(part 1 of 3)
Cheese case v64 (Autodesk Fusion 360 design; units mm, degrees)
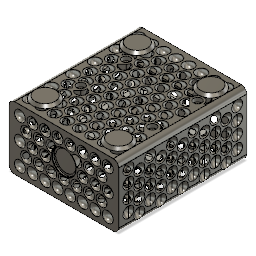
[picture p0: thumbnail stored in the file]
parameter "thickness" = 6.234
parameter "radius" = 5.3988 (= "thickness * sqrt(3) / 2")
parameter "bootm_width" = 108.8712 (= "2 * hor_idents + bottom_front_big_x * 2 * x - 2 * x + 2 * radius")
parameter "bottom_height" = 127.4117 (= "2 * ver_idents + ( bottom_front_big_y ) * 4 * radius - 2 * radius")
parameter "hor_idents" = 5.3988 (= "radius")
parameter "ver_idents" = 4.319 (= "radius / 1.25")
parameter "minimal_feature" = 1.6704 (= "2 * ( x - radius )")
parameter "front_height" = 62.6261 (= "2 * ver_idents + ( 3 ) * 4 * radius - 2 * radius")
base_feature "Base Feature1"
sketch "Sketch1" plane through (0, 0, 0) normal (0, 0, -1) x axis (-1, 0, 0)
  line L1 (42.5, 25) -> (42.5, -25)
  line L2 (-39.5, 28) -> (39.5, 28)
  line L3 (-42.5, -25) -> (-42.5, 25)
  line L4 (39.5, -28) -> (-39.5, -28)
  arc A1 centre (39.5, 25) radius 3 clockwise from (39.5, 28) to (42.5, 25)
  arc A2 centre (-39.5, 25) radius 3 clockwise from (-42.5, 25) to (-39.5, 28)
  arc A3 centre (-39.5, -25) radius 3 clockwise from (-39.5, -28) to (-42.5, -25)
  arc A4 centre (39.5, -25) radius 3 clockwise from (42.5, -25) to (39.5, -28)
  circle C1 centre (39, -24.5) radius 1.375
  circle C2 centre (-19, 24.5) radius 1.375
  circle C3 centre (-19, -24.5) radius 1.375
  circle C4 centre (39, 24.5) radius 1.375
extrude "Extrude1" add sketch "Sketch1" profile of C4 along a picked direction blind -14.9 named "d69_1"
base_feature "Base Feature1"
base_feature "Base Feature1"
base_feature "Base Feature1"
base_feature "Base Feature1"
base_feature "Base Feature1"
base_feature "Base Feature1"
base_feature "Base Feature1"
position "Position1"
sketch "Sketch1" plane through (0, 0, 0) normal (0, 1, 0) x axis (1, 0, 0)
  line L1 (108.8712, 0) -> (0, 0)
  line L2 (108.8712, 127.4117) -> (108.8712, 0)
  line L3 (0, 127.4117) -> (108.8712, 127.4117)
  line L4 (0, 0) -> (0, 127.4117)
  point P1 (0, 0)
  point P2 (0, 0)
  point P3 (108.8712, 0)
  point P5 (0, 127.4117)
  horizontal L1
  vertical L2
  horizontal L3
  vertical L4
  coincident P1 P2
  dimension "d129" distance P2 P3 = 108.8712 (= "bootm_width")
  dimension "d130" distance P2 P5 = 127.4117 (= "bottom_height")
extrude "Extrude1" new body sketch "Sketch1" along normal blind 6.234 (= "thickness")
position "Position2"
sketch "Sketch2" plane through (0, 0, 0) normal (0, 0, 1) x axis (1, 0, 0)
  line L1 (108.8712, 0) -> (0, 0)
  line L2 (108.8712, 6.234) -> (108.8712, 0)
  line L3 (0, 6.234) -> (108.8712, 6.234)
  line L4 (0, 0) -> (0, 6.234)
  line L5 (108.8712, 6.234) -> (0, 6.234)
  line L6 (108.8712, -56.3921) -> (108.8712, 6.234)
  line L7 (0, -56.3921) -> (108.8712, -56.3921)
  line L8 (0, 6.234) -> (0, -56.3921)
  point P5 (0, 6.234)
  point P6 (0, 6.234)
  point P7 (108.8712, 6.234)
  point P9 (0, -56.3921)
  horizontal L5
  vertical L6
  horizontal L7
  vertical L8
  coincident P5 P6
  dimension "d133" distance P6 P7 = 108.8712 (= "bootm_width")
  dimension "d134" distance P6 P9 = 62.6261 (= "front_height")
position "Position3"
extrude "Extrude2" new body sketch "Sketch2" no distance stored bodies "Vorne"
sketch "Sketch3" plane through (0, 0, 0) normal (0, 0, 1) x axis (1, 0, 0)
  line L1 (108.8712, -56.3921) -> (0, -56.3921)
  line L2 (108.8712, 6.234) -> (108.8712, -56.3921)
  line L3 (0, 6.234) -> (108.8712, 6.234)
  line L4 (0, -56.3921) -> (0, 6.234)
  line L5 (108.8712, -56.3921) -> (0, -56.3921)
  line L6 (108.8712, -50.1581) -> (108.8712, -56.3921)
  line L7 (0, -50.1581) -> (108.8712, -50.1581)
  line L8 (0, -56.3921) -> (0, -50.1581)
  point P2 (0, -56.3921)
  point P6 (0, -56.3921)
  point P7 (108.8712, -56.3921)
  point P9 (0, -50.1581)
  horizontal L5
  vertical L6
  horizontal L7
  vertical L8
  coincident P2 P6
  dimension "d137" distance P6 P7 = 108.8712 (= "bootm_width")
  dimension "d138" distance P6 P9 = 6.234 (= "thickness")
sketch "Sketch4" plane through (108.8712, 0, 0) normal (1, 0, 0) x axis (0, 0, -1)
  line L1 (127.4117, 0) -> (0, 0)
  line L2 (127.4117, 6.234) -> (127.4117, 0)
  line L3 (0, 6.234) -> (127.4117, 6.234)
  line L4 (0, 0) -> (0, 6.234)
  line L5 (127.4117, 6.234) -> (0, 6.234)
  line L6 (127.4117, -56.3921) -> (127.4117, 6.234)
  line L7 (0, -56.3921) -> (127.4117, -56.3921)
  line L8 (0, 6.234) -> (0, -56.3921)
  point P5 (0, 6.234)
  point P6 (0, 6.234)
  point P7 (127.4117, 6.234)
  point P9 (0, -56.3921)
  horizontal L5
  vertical L6
  horizontal L7
  vertical L8
  coincident P5 P6
  dimension "d141" distance P6 P7 = 127.4117 (= "bottom_height")
  dimension "d142" distance P6 P9 = 62.6261 (= "front_height")
extrude "Extrude4" new body sketch "Sketch4" no distance stored bodies "Links"
sketch "Sketch5" plane through (0, 0, 0) normal (-1, 0, 0) x axis (0, 0, 1)
  line L1 (0, 0) -> (-127.4117, 0)
  line L2 (0, 6.234) -> (0, 0)
  line L3 (-127.4117, 6.234) -> (0, 6.234)
  line L4 (-127.4117, 0) -> (-127.4117, 6.234)
  line L5 (-127.4117, 6.234) -> (0, 6.234)
  line L6 (-127.4117, -56.3921) -> (-127.4117, 6.234)
  line L7 (0, -56.3921) -> (-127.4117, -56.3921)
  line L8 (0, 6.234) -> (0, -56.3921)
  point P4 (0, 6.234)
  point P6 (0, 6.234)
  point P7 (-127.4117, 6.234)
  point P9 (0, -56.3921)
  horizontal L5
  vertical L6
  horizontal L7
  vertical L8
  coincident P4 P6
  dimension "d145" distance P6 P7 = 127.4117 (= "bottom_height")
  dimension "d146" distance P6 P9 = 62.6261 (= "front_height")
position "Position4"
position "Position5"
position "Position6"
sketch "Bottom outside" plane through (0, 6.234, 0) normal (0, 1, 0) x axis (-1, 0, 0)
  line L1 (0, 0) -> (0, -127.4117)
  line L2 (-108.8712, 0) -> (0, 0)
  line L3 (-108.8712, -127.4117) -> (-108.8712, 0)
  line L4 (0, -127.4117) -> (-108.8712, -127.4117)
  line L5 (-17.0316, -25.9143) -> (-17.0316, -20.5154)
  line L6 (-10.7976, -15.1166) -> (-10.7976, -9.7178)
  line L7 (-17.0316, -15.1166) -> (-17.0316, -20.5154)
  line L8 (-17.0316, -20.5154) -> (-17.0316, -9.7178)
  line L9 (-10.7976, -4.319) -> (-10.7976, -9.7178)
  line L10 (-17.0316, -9.7178) -> (-10.7976, -9.7178)
  line L11 (-5.3988, -50) -> (-5.3988, 0)
  line L12 (-96.4032, -4.319) -> (0, -4.319)
  line L13 (-29.4996, -25.9143) -> (-29.4996, -20.5154)
  line L14 (-29.4996, -15.1166) -> (-29.4996, -20.5154)
  line L15 (-41.9676, -25.9143) -> (-41.9676, -20.5154)
  line L16 (-41.9676, -15.1166) -> (-41.9676, -20.5154)
  line L17 (-54.4356, -25.9143) -> (-54.4356, -20.5154)
  line L18 (-54.4356, -15.1166) -> (-54.4356, -20.5154)
  line L19 (-66.9036, -25.9143) -> (-66.9036, -20.5154)
  line L20 (-66.9036, -15.1166) -> (-66.9036, -20.5154)
  line L21 (-79.3716, -25.9143) -> (-79.3716, -20.5154)
  line L22 (-79.3716, -15.1166) -> (-79.3716, -20.5154)
  line L23 (-91.8396, -25.9143) -> (-91.8396, -20.5154)
  line L24 (-91.8396, -15.1166) -> (-91.8396, -20.5154)
  line L25 (-17.0316, -47.5095) -> (-17.0316, -42.1107)
  line L26 (-17.0316, -36.7119) -> (-17.0316, -42.1107)
  line L27 (-29.4996, -47.5095) -> (-29.4996, -42.1107)
  line L28 (-29.4996, -36.7119) -> (-29.4996, -42.1107)
  line L29 (-41.9676, -47.5095) -> (-41.9676, -42.1107)
  line L30 (-41.9676, -36.7119) -> (-41.9676, -42.1107)
  line L31 (-54.4356, -47.5095) -> (-54.4356, -42.1107)
  line L32 (-54.4356, -36.7119) -> (-54.4356, -42.1107)
  line L33 (-66.9036, -47.5095) -> (-66.9036, -42.1107)
  line L34 (-66.9036, -36.7119) -> (-66.9036, -42.1107)
  line L35 (-79.3716, -47.5095) -> (-79.3716, -42.1107)
  line L36 (-79.3716, -36.7119) -> (-79.3716, -42.1107)
  line L37 (-91.8396, -47.5095) -> (-91.8396, -42.1107)
  line L38 (-91.8396, -36.7119) -> (-91.8396, -42.1107)
  line L39 (-17.0316, -69.1047) -> (-17.0316, -63.7059)
  line L40 (-17.0316, -58.3071) -> (-17.0316, -63.7059)
  line L41 (-29.4996, -69.1047) -> (-29.4996, -63.7059)
  line L42 (-29.4996, -58.3071) -> (-29.4996, -63.7059)
  line L43 (-41.9676, -69.1047) -> (-41.9676, -63.7059)
  line L44 (-41.9676, -58.3071) -> (-41.9676, -63.7059)
  line L45 (-54.4356, -69.1047) -> (-54.4356, -63.7059)
  line L46 (-54.4356, -58.3071) -> (-54.4356, -63.7059)
  line L47 (-66.9036, -69.1047) -> (-66.9036, -63.7059)
  line L48 (-66.9036, -58.3071) -> (-66.9036, -63.7059)
  line L49 (-79.3716, -69.1047) -> (-79.3716, -63.7059)
  line L50 (-79.3716, -58.3071) -> (-79.3716, -63.7059)
  line L51 (-91.8396, -69.1047) -> (-91.8396, -63.7059)
  line L52 (-91.8396, -58.3071) -> (-91.8396, -63.7059)
  line L53 (-17.0316, -90.6999) -> (-17.0316, -85.3011)
  line L54 (-17.0316, -79.9023) -> (-17.0316, -85.3011)
  line L55 (-29.4996, -90.6999) -> (-29.4996, -85.3011)
  line L56 (-29.4996, -79.9023) -> (-29.4996, -85.3011)
  line L57 (-41.9676, -90.6999) -> (-41.9676, -85.3011)
  line L58 (-41.9676, -79.9023) -> (-41.9676, -85.3011)
  line L59 (-54.4356, -90.6999) -> (-54.4356, -85.3011)
  line L60 (-54.4356, -79.9023) -> (-54.4356, -85.3011)
  line L61 (-66.9036, -90.6999) -> (-66.9036, -85.3011)
  line L62 (-66.9036, -79.9023) -> (-66.9036, -85.3011)
  line L63 (-79.3716, -90.6999) -> (-79.3716, -85.3011)
  line L64 (-79.3716, -79.9023) -> (-79.3716, -85.3011)
  line L65 (-91.8396, -90.6999) -> (-91.8396, -85.3011)
  line L66 (-91.8396, -79.9023) -> (-91.8396, -85.3011)
  line L67 (-23.2656, -15.1166) -> (-23.2656, -9.7178)
  line L68 (-23.2656, -4.319) -> (-23.2656, -9.7178)
  line L69 (-35.7336, -15.1166) -> (-35.7336, -9.7178)
  line L70 (-35.7336, -4.319) -> (-35.7336, -9.7178)
  line L71 (-48.2016, -15.1166) -> (-48.2016, -9.7178)
  line L72 (-48.2016, -4.319) -> (-48.2016, -9.7178)
  line L73 (-60.6696, -15.1166) -> (-60.6696, -9.7178)
  line L74 (-60.6696, -4.319) -> (-60.6696, -9.7178)
  line L75 (-73.1376, -15.1166) -> (-73.1376, -9.7178)
  line L76 (-73.1376, -4.319) -> (-73.1376, -9.7178)
  line L77 (-85.6056, -15.1166) -> (-85.6056, -9.7178)
  line L78 (-85.6056, -4.319) -> (-85.6056, -9.7178)
  line L79 (-98.0736, -15.1166) -> (-98.0736, -9.7178)
  line L80 (-98.0736, -4.319) -> (-98.0736, -9.7178)
  line L81 (-10.7976, -36.7119) -> (-10.7976, -31.3131)
  line L82 (-10.7976, -25.9143) -> (-10.7976, -31.3131)
  line L83 (-23.2656, -36.7119) -> (-23.2656, -31.3131)
  line L84 (-23.2656, -25.9143) -> (-23.2656, -31.3131)
  line L85 (-35.7336, -36.7119) -> (-35.7336, -31.3131)
  line L86 (-35.7336, -25.9143) -> (-35.7336, -31.3131)
  line L87 (-48.2016, -36.7119) -> (-48.2016, -31.3131)
  line L88 (-48.2016, -25.9143) -> (-48.2016, -31.3131)
  line L89 (-60.6696, -36.7119) -> (-60.6696, -31.3131)
  line L90 (-60.6696, -25.9143) -> (-60.6696, -31.3131)
  line L91 (-73.1376, -36.7119) -> (-73.1376, -31.3131)
  line L92 (-73.1376, -25.9143) -> (-73.1376, -31.3131)
  line L93 (-85.6056, -36.7119) -> (-85.6056, -31.3131)
  line L94 (-85.6056, -25.9143) -> (-85.6056, -31.3131)
  line L95 (-98.0736, -36.7119) -> (-98.0736, -31.3131)
  line L96 (-98.0736, -25.9143) -> (-98.0736, -31.3131)
  line L97 (-10.7976, -58.3071) -> (-10.7976, -52.9083)
  line L98 (-10.7976, -47.5095) -> (-10.7976, -52.9083)
  line L99 (-23.2656, -58.3071) -> (-23.2656, -52.9083)
  line L100 (-23.2656, -47.5095) -> (-23.2656, -52.9083)
  line L101 (-35.7336, -58.3071) -> (-35.7336, -52.9083)
  line L102 (-35.7336, -47.5095) -> (-35.7336, -52.9083)
  line L103 (-48.2016, -58.3071) -> (-48.2016, -52.9083)
  line L104 (-48.2016, -47.5095) -> (-48.2016, -52.9083)
  line L105 (-60.6696, -58.3071) -> (-60.6696, -52.9083)
  line L106 (-60.6696, -47.5095) -> (-60.6696, -52.9083)
  line L107 (-73.1376, -58.3071) -> (-73.1376, -52.9083)
  line L108 (-73.1376, -47.5095) -> (-73.1376, -52.9083)
  line L109 (-85.6056, -58.3071) -> (-85.6056, -52.9083)
  line L110 (-85.6056, -47.5095) -> (-85.6056, -52.9083)
  line L111 (-98.0736, -58.3071) -> (-98.0736, -52.9083)
  line L112 (-98.0736, -47.5095) -> (-98.0736, -52.9083)
  line L113 (-10.7976, -79.9023) -> (-10.7976, -74.5035)
  line L114 (-10.7976, -69.1047) -> (-10.7976, -74.5035)
  line L115 (-23.2656, -79.9023) -> (-23.2656, -74.5035)
  line L116 (-23.2656, -69.1047) -> (-23.2656, -74.5035)
  line L117 (-35.7336, -79.9023) -> (-35.7336, -74.5035)
  line L118 (-35.7336, -69.1047) -> (-35.7336, -74.5035)
  line L119 (-48.2016, -79.9023) -> (-48.2016, -74.5035)
  line L120 (-48.2016, -69.1047) -> (-48.2016, -74.5035)
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  point P12 (-10.7976, -9.7178)
  point P13 (-10.7976, -9.7178)
  point P15 (-17.0316, -20.5154)
  point P16 (-17.0316, -20.5154)
  point P17 (-10.7976, -9.7178)
  point P20 (-17.0316, -20.5154)
  point P22 (-17.0316, -15.1166)
  point P14 (-17.0316, -9.7178)
  point P19 (-10.7976, -4.319)
  coincident P12 P13
  horizontal L10
  perpendicular L8 L10
  coincident P15 P16
  coincident P12 P17
  perpendicular L6 L10
  perpendicular L9 L12
  coincident P16 P20
  parallel L5 L8
  midpoint P22 L8
  dimension "d181" radius = 5.3988 (= "radius")
  dimension "d182" distance P13 P14 = 6.234 (= "Linear Dimension-2")
  dimension "d183" distance P14 P15 = 10.7976 (= "2 * radius")
  dimension "d184" diameter = 10.7976 (= "2 * radius")
  dimension "d185" distance P13 P19 = 5.3988 (= "radius")
  dimension "d189" R-Pattern1-vDistance = -21.5952 (= "-4 * radius")
  dimension "d193" R-Pattern2-vDistance = 21.5952 (= "4 * radius")
sketch "Bottom inside" plane through (0, 0, 0) normal (0, -1, 0) x axis (1, 0, 0)
  line L1 (108.8712, -127.4117) -> (0, -127.4117)
  line L2 (0, 0) -> (108.8712, 0)
  line L3 (23.2656, -29.5135) -> (23.2656, -24.1147)
  line L4 (17.0316, -13.317) -> (17.0316, -9.7178)
  line L5 (17.0316, -18.7158) -> (17.0316, -13.317)
  line L6 (23.2656, -18.7158) -> (23.2656, -24.1147)
  line L7 (17.0316, -9.7178) -> (10.7976, -9.7178)
  line L8 (17.0316, -7.9182) -> (17.0316, -13.317)
  line L9 (17.0316, -20.5154) -> (17.0316, -9.7178)
  line L10 (23.2656, -24.1147) -> (23.2656, -13.317)
  line L11 (23.2656, -13.317) -> (17.0316, -13.317)
  line L12 (29.4996, -18.7158) -> (29.4996, -13.317)
  line L13 (29.4996, -20.5154) -> (29.4996, -9.7178)
  line L14 (29.4996, -7.9182) -> (29.4996, -13.317)
  line L15 (41.9676, -18.7158) -> (41.9676, -13.317)
  line L16 (41.9676, -20.5154) -> (41.9676, -9.7178)
  line L17 (41.9676, -7.9182) -> (41.9676, -13.317)
  line L18 (54.4356, -18.7158) -> (54.4356, -13.317)
  line L19 (54.4356, -20.5154) -> (54.4356, -9.7178)
  line L20 (54.4356, -7.9182) -> (54.4356, -13.317)
  line L21 (66.9036, -18.7158) -> (66.9036, -13.317)
  line L22 (66.9036, -20.5154) -> (66.9036, -9.7178)
  line L23 (66.9036, -7.9182) -> (66.9036, -13.317)
  line L24 (79.3716, -18.7158) -> (79.3716, -13.317)
  line L25 (79.3716, -20.5154) -> (79.3716, -9.7178)
  line L26 (79.3716, -7.9182) -> (79.3716, -13.317)
  line L27 (91.8396, -18.7158) -> (91.8396, -13.317)
  line L28 (91.8396, -20.5154) -> (91.8396, -9.7178)
  line L29 (91.8396, -7.9182) -> (91.8396, -13.317)
  line L30 (17.0316, -40.3111) -> (17.0316, -34.9123)
  line L31 (17.0316, -42.1107) -> (17.0316, -31.3131)
  line L32 (17.0316, -29.5135) -> (17.0316, -34.9123)
  line L33 (29.4996, -40.3111) -> (29.4996, -34.9123)
  line L34 (29.4996, -42.1107) -> (29.4996, -31.3131)
  line L35 (29.4996, -29.5135) -> (29.4996, -34.9123)
  line L36 (41.9676, -40.3111) -> (41.9676, -34.9123)
  line L37 (41.9676, -42.1107) -> (41.9676, -31.3131)
  line L38 (41.9676, -29.5135) -> (41.9676, -34.9123)
  line L39 (54.4356, -40.3111) -> (54.4356, -34.9123)
  line L40 (54.4356, -42.1107) -> (54.4356, -31.3131)
  line L41 (54.4356, -29.5135) -> (54.4356, -34.9123)
  line L42 (66.9036, -40.3111) -> (66.9036, -34.9123)
  line L43 (66.9036, -42.1107) -> (66.9036, -31.3131)
  line L44 (66.9036, -29.5135) -> (66.9036, -34.9123)
  line L45 (79.3716, -40.3111) -> (79.3716, -34.9123)
  line L46 (79.3716, -42.1107) -> (79.3716, -31.3131)
  line L47 (79.3716, -29.5135) -> (79.3716, -34.9123)
  line L48 (91.8396, -40.3111) -> (91.8396, -34.9123)
  line L49 (91.8396, -42.1107) -> (91.8396, -31.3131)
  line L50 (91.8396, -29.5135) -> (91.8396, -34.9123)
  line L51 (17.0316, -61.9063) -> (17.0316, -56.5075)
  line L52 (17.0316, -63.7059) -> (17.0316, -52.9083)
  line L53 (17.0316, -51.1087) -> (17.0316, -56.5075)
  line L54 (29.4996, -61.9063) -> (29.4996, -56.5075)
  line L55 (29.4996, -63.7059) -> (29.4996, -52.9083)
  line L56 (29.4996, -51.1087) -> (29.4996, -56.5075)
  line L57 (41.9676, -61.9063) -> (41.9676, -56.5075)
  line L58 (41.9676, -63.7059) -> (41.9676, -52.9083)
  line L59 (41.9676, -51.1087) -> (41.9676, -56.5075)
  line L60 (54.4356, -61.9063) -> (54.4356, -56.5075)
  line L61 (54.4356, -63.7059) -> (54.4356, -52.9083)
  line L62 (54.4356, -51.1087) -> (54.4356, -56.5075)
  line L63 (66.9036, -61.9063) -> (66.9036, -56.5075)
  line L64 (66.9036, -63.7059) -> (66.9036, -52.9083)
  line L65 (66.9036, -51.1087) -> (66.9036, -56.5075)
  line L66 (79.3716, -61.9063) -> (79.3716, -56.5075)
  line L67 (79.3716, -63.7059) -> (79.3716, -52.9083)
  line L68 (79.3716, -51.1087) -> (79.3716, -56.5075)
  line L69 (91.8396, -61.9063) -> (91.8396, -56.5075)
  line L70 (91.8396, -63.7059) -> (91.8396, -52.9083)
  line L71 (91.8396, -51.1087) -> (91.8396, -56.5075)
  line L72 (17.0316, -83.5015) -> (17.0316, -78.1027)
  line L73 (17.0316, -85.3011) -> (17.0316, -74.5035)
  line L74 (17.0316, -72.7039) -> (17.0316, -78.1027)
  line L75 (29.4996, -83.5015) -> (29.4996, -78.1027)
  line L76 (29.4996, -85.3011) -> (29.4996, -74.5035)
  line L77 (29.4996, -72.7039) -> (29.4996, -78.1027)
  line L78 (41.9676, -83.5015) -> (41.9676, -78.1027)
  line L79 (41.9676, -85.3011) -> (41.9676, -74.5035)
  line L80 (41.9676, -72.7039) -> (41.9676, -78.1027)
  line L81 (54.4356, -83.5015) -> (54.4356, -78.1027)
  line L82 (54.4356, -85.3011) -> (54.4356, -74.5035)
  line L83 (54.4356, -72.7039) -> (54.4356, -78.1027)
  line L84 (66.9036, -83.5015) -> (66.9036, -78.1027)
  line L85 (66.9036, -85.3011) -> (66.9036, -74.5035)
  line L86 (66.9036, -72.7039) -> (66.9036, -78.1027)
  line L87 (79.3716, -83.5015) -> (79.3716, -78.1027)
  line L88 (79.3716, -85.3011) -> (79.3716, -74.5035)
  line L89 (79.3716, -72.7039) -> (79.3716, -78.1027)
  line L90 (91.8396, -83.5015) -> (91.8396, -78.1027)
  line L91 (91.8396, -85.3011) -> (91.8396, -74.5035)
  line L92 (91.8396, -72.7039) -> (91.8396, -78.1027)
  line L93 (17.0316, -105.0967) -> (17.0316, -99.6979)
  line L94 (17.0316, -106.8963) -> (17.0316, -96.0987)
  line L95 (17.0316, -94.2991) -> (17.0316, -99.6979)
  line L96 (29.4996, -105.0967) -> (29.4996, -99.6979)
  line L97 (29.4996, -106.8963) -> (29.4996, -96.0987)
  line L98 (29.4996, -94.2991) -> (29.4996, -99.6979)
  line L99 (41.9676, -105.0967) -> (41.9676, -99.6979)
  line L100 (41.9676, -106.8963) -> (41.9676, -96.0987)
  line L101 (41.9676, -94.2991) -> (41.9676, -99.6979)
  line L102 (54.4356, -105.0967) -> (54.4356, -99.6979)
  line L103 (54.4356, -106.8963) -> (54.4356, -96.0987)
  line L104 (54.4356, -94.2991) -> (54.4356, -99.6979)
  line L105 (66.9036, -105.0967) -> (66.9036, -99.6979)
  line L106 (66.9036, -106.8963) -> (66.9036, -96.0987)
  line L107 (66.9036, -94.2991) -> (66.9036, -99.6979)
  line L108 (79.3716, -105.0967) -> (79.3716, -99.6979)
  line L109 (79.3716, -106.8963) -> (79.3716, -96.0987)
  line L110 (79.3716, -94.2991) -> (79.3716, -99.6979)
  line L111 (91.8396, -105.0967) -> (91.8396, -99.6979)
  line L112 (91.8396, -106.8963) -> (91.8396, -96.0987)
  line L113 (91.8396, -94.2991) -> (91.8396, -99.6979)
  line L114 (35.7336, -29.5135) -> (35.7336, -24.1147)
  line L115 (35.7336, -18.7158) -> (35.7336, -24.1147)
  line L116 (48.2016, -29.5135) -> (48.2016, -24.1147)
  line L117 (48.2016, -18.7158) -> (48.2016, -24.1147)
  line L118 (60.6696, -29.5135) -> (60.6696, -24.1147)
  line L119 (60.6696, -18.7158) -> (60.6696, -24.1147)
  line L120 (73.1376, -29.5135) -> (73.1376, -24.1147)
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  point P17 (17.0316, -9.7178)
  point P24 (17.0316, -9.7178)
  point P6 (17.0316, -13.317)
  point P18 (17.0316, -13.317)
  point P11 (23.2656, -24.1147)
  point P20 (23.2656, -24.1147)
  point P22 (23.2656, -24.1147)
  point P19 (17.0316, -18.7158)
  point P9 (17.0316, -7.9182)
  point P10 (23.2656, -13.317)
  point P21 (23.2656, -18.7158)
  point P23 (23.2656, -29.5135)
  coincident P17 P24
  perpendicular L4 L7
  coincident P6 P18
  parallel L5 L9
  parallel L8 L9
  perpendicular L9 L11
  equal L7 L11
  perpendicular L10 L11
  coincident P11 P20
  parallel L6 L10
  coincident P20 P22
  parallel L3 L10
  dimension "d196" distance P17 P18 = 3.5992 (= "Linear Dimension-2")
  dimension "d197" diameter = 10.7976 (= "2 * radius")
  dimension "d198" distance P18 P19 = 5.3988 (= "radius")
  dimension "d199" distance P9 P18 = 5.3988 (= "radius")
  dimension "d200" distance P10 P11 = 10.7976 (= "2 * radius")
  dimension "d201" diameter = 10.7976 (= "2 * radius")
  dimension "d202" distance P11 P21 = 5.3988 (= "radius")
  dimension "d203" distance P22 P23 = 5.3988 (= "radius")
  dimension "d207" R-Pattern1-vDistance = 21.5952 (= "4 * radius")
  dimension "d211" R-Pattern2-vDistance = 21.5952 (= "4 * radius")
  dimension "d215" R-Pattern3-vDistance = 21.5952 (= "4 * radius")
revolve "Revolve79" sketch "Bottom outside" AlongAngle 360
revolve "Revolve2" sketch "Bottom outside" AlongAngle 360
revolve "Revolve3" sketch "Bottom outside" AlongAngle 360
revolve "Revolve4" sketch "Bottom outside" AlongAngle 360
revolve "Revolve5" sketch "Bottom outside" AlongAngle 360
revolve "Revolve6" sketch "Bottom outside" AlongAngle 360
revolve "Revolve7" sketch "Bottom outside" AlongAngle 360
revolve "Revolve8" sketch "Bottom outside" AlongAngle 360
revolve "Revolve9" sketch "Bottom outside" AlongAngle 360
revolve "Revolve10" sketch "Bottom outside" AlongAngle 360
revolve "Revolve11" sketch "Bottom outside" AlongAngle 360
revolve "Revolve12" sketch "Bottom outside" AlongAngle 360
revolve "Revolve13" sketch "Bottom outside" AlongAngle 360
revolve "Revolve14" sketch "Bottom outside" AlongAngle 360
revolve "Revolve15" sketch "Bottom outside" AlongAngle 360
revolve "Revolve80" sketch "Bottom inside" AlongAngle 360
revolve "Revolve17" sketch "Bottom inside" AlongAngle 360
revolve "Revolve18" sketch "Bottom inside" AlongAngle 360
revolve "Revolve19" sketch "Bottom inside" AlongAngle 360
revolve "Revolve20" sketch "Bottom inside" AlongAngle 360
revolve "Revolve21" sketch "Bottom inside" AlongAngle 360
revolve "Revolve22" sketch "Bottom inside" AlongAngle 360
revolve "Revolve23" sketch "Bottom inside" AlongAngle 360
revolve "Revolve24" sketch "Bottom inside" AlongAngle 360
revolve "Revolve25" sketch "Bottom inside" AlongAngle 360
revolve "Revolve26" sketch "Bottom inside" AlongAngle 360
revolve "Revolve27" sketch "Bottom inside" AlongAngle 360
revolve "Revolve28" sketch "Bottom inside" AlongAngle 360
revolve "Revolve29" sketch "Bottom inside" AlongAngle 360
revolve "Revolve30" sketch "Bottom inside" AlongAngle 360
work_plane "WorkPlane1" AlongDistance -31.3131 (= "-front_height / 2")
mirror "Mirror1" bodies "Deckel"
sketch "Front outside" plane through (0, 0, 0) normal (0, 0, 1) x axis (1, 0, 0)
  line L1 (108.8712, -56.3921) -> (0, -56.3921)
  line L2 (108.8712, 6.234) -> (108.8712, -56.3921)
  line L3 (0, 6.234) -> (108.8712, 6.234)
  line L4 (0, -56.3921) -> (0, 6.234)
  line L5 (5.3988, -6.3921) -> (5.3988, -56.3921)
  line L6 (17.0316, -30.4779) -> (17.0316, -35.8767)
  line L7 (17.0316, -46.6743) -> (10.7976, -46.6743)
  line L8 (10.7976, -41.2755) -> (10.7976, -46.6743)
  line L9 (17.0316, -41.2755) -> (17.0316, -35.8767)
  line L10 (10.7976, -52.0731) -> (10.7976, -46.6743)
  line L11 (17.0316, -35.8767) -> (17.0316, -46.6743)
  line L12 (96.4032, -52.0731) -> (0, -52.0731)
  line L13 (23.2656, -41.2755) -> (23.2656, -46.6743)
  line L14 (23.2656, -52.0731) -> (23.2656, -46.6743)
  line L15 (35.7336, -41.2755) -> (35.7336, -46.6743)
  line L16 (35.7336, -52.0731) -> (35.7336, -46.6743)
  line L17 (48.2016, -41.2755) -> (48.2016, -46.6743)
  line L18 (48.2016, -52.0731) -> (48.2016, -46.6743)
  line L19 (60.6696, -41.2755) -> (60.6696, -46.6743)
  line L20 (60.6696, -52.0731) -> (60.6696, -46.6743)
  line L21 (73.1376, -41.2755) -> (73.1376, -46.6743)
  line L22 (73.1376, -52.0731) -> (73.1376, -46.6743)
  line L23 (85.6056, -41.2755) -> (85.6056, -46.6743)
  line L24 (85.6056, -52.0731) -> (85.6056, -46.6743)
  line L25 (98.0736, -41.2755) -> (98.0736, -46.6743)
  line L26 (98.0736, -52.0731) -> (98.0736, -46.6743)
  line L27 (10.7976, -19.6803) -> (10.7976, -25.0791)
  line L28 (10.7976, -30.4779) -> (10.7976, -25.0791)
  line L29 (23.2656, -19.6803) -> (23.2656, -25.0791)
  line L30 (23.2656, -30.4779) -> (23.2656, -25.0791)
  line L31 (35.7336, -19.6803) -> (35.7336, -25.0791)
  line L32 (35.7336, -30.4779) -> (35.7336, -25.0791)
  line L33 (48.2016, -19.6803) -> (48.2016, -25.0791)
  line L34 (48.2016, -30.4779) -> (48.2016, -25.0791)
  line L35 (60.6696, -19.6803) -> (60.6696, -25.0791)
  line L36 (60.6696, -30.4779) -> (60.6696, -25.0791)
  line L37 (73.1376, -19.6803) -> (73.1376, -25.0791)
  line L38 (73.1376, -30.4779) -> (73.1376, -25.0791)
  line L39 (85.6056, -19.6803) -> (85.6056, -25.0791)
  line L40 (85.6056, -30.4779) -> (85.6056, -25.0791)
  line L41 (98.0736, -19.6803) -> (98.0736, -25.0791)
  line L42 (98.0736, -30.4779) -> (98.0736, -25.0791)
  line L43 (10.7976, 1.915) -> (10.7976, -3.4838)
  line L44 (10.7976, -8.8826) -> (10.7976, -3.4838)
  line L45 (23.2656, 1.915) -> (23.2656, -3.4838)
  line L46 (23.2656, -8.8826) -> (23.2656, -3.4838)
  line L47 (35.7336, 1.915) -> (35.7336, -3.4838)
  line L48 (35.7336, -8.8826) -> (35.7336, -3.4838)
  line L49 (48.2016, 1.915) -> (48.2016, -3.4838)
  line L50 (48.2016, -8.8826) -> (48.2016, -3.4838)
  line L51 (60.6696, 1.915) -> (60.6696, -3.4838)
  line L52 (60.6696, -8.8826) -> (60.6696, -3.4838)
  line L53 (73.1376, 1.915) -> (73.1376, -3.4838)
  line L54 (73.1376, -8.8826) -> (73.1376, -3.4838)
  line L55 (85.6056, 1.915) -> (85.6056, -3.4838)
  line L56 (85.6056, -8.8826) -> (85.6056, -3.4838)
  line L57 (98.0736, 1.915) -> (98.0736, -3.4838)
  line L58 (98.0736, -8.8826) -> (98.0736, -3.4838)
  line L59 (29.4996, -30.4779) -> (29.4996, -35.8767)
  line L60 (29.4996, -41.2755) -> (29.4996, -35.8767)
  line L61 (41.9676, -30.4779) -> (41.9676, -35.8767)
  line L62 (41.9676, -41.2755) -> (41.9676, -35.8767)
  line L63 (54.4356, -30.4779) -> (54.4356, -35.8767)
  line L64 (54.4356, -41.2755) -> (54.4356, -35.8767)
  line L65 (66.9036, -30.4779) -> (66.9036, -35.8767)
  line L66 (66.9036, -41.2755) -> (66.9036, -35.8767)
  line L67 (79.3716, -30.4779) -> (79.3716, -35.8767)
  line L68 (79.3716, -41.2755) -> (79.3716, -35.8767)
  line L69 (91.8396, -30.4779) -> (91.8396, -35.8767)
  line L70 (91.8396, -41.2755) -> (91.8396, -35.8767)
  line L71 (17.0316, -8.8826) -> (17.0316, -14.2814)
  line L72 (17.0316, -19.6803) -> (17.0316, -14.2814)
  line L73 (29.4996, -8.8826) -> (29.4996, -14.2814)
  line L74 (29.4996, -19.6803) -> (29.4996, -14.2814)
  line L75 (41.9676, -8.8826) -> (41.9676, -14.2814)
  line L76 (41.9676, -19.6803) -> (41.9676, -14.2814)
  line L77 (54.4356, -8.8826) -> (54.4356, -14.2814)
  line L78 (54.4356, -19.6803) -> (54.4356, -14.2814)
  line L79 (66.9036, -8.8826) -> (66.9036, -14.2814)
  line L80 (66.9036, -19.6803) -> (66.9036, -14.2814)
  line L81 (79.3716, -8.8826) -> (79.3716, -14.2814)
  line L82 (79.3716, -19.6803) -> (79.3716, -14.2814)
  line L83 (91.8396, -8.8826) -> (91.8396, -14.2814)
  line L84 (91.8396, -19.6803) -> (91.8396, -14.2814)
  circle C1 centre (10.7976, -46.6743) radius 5.3988
  circle C2 centre (17.0316, -35.8767) radius 5.3988
  circle C3 centre (23.2656, -46.6743) radius 5.3988
  circle C4 centre (35.7336, -46.6743) radius 5.3988
  circle C5 centre (48.2016, -46.6743) radius 5.3988
  circle C6 centre (60.6696, -46.6743) radius 5.3988
  circle C7 centre (73.1376, -46.6743) radius 5.3988
  circle C8 centre (85.6056, -46.6743) radius 5.3988
  circle C9 centre (98.0736, -46.6743) radius 5.3988
  circle C10 centre (10.7976, -25.0791) radius 5.3988
  circle C11 centre (23.2656, -25.0791) radius 5.3988
  circle C12 centre (35.7336, -25.0791) radius 5.3988
  circle C13 centre (48.2016, -25.0791) radius 5.3988
  circle C14 centre (60.6696, -25.0791) radius 5.3988
  circle C15 centre (73.1376, -25.0791) radius 5.3988
  circle C16 centre (85.6056, -25.0791) radius 5.3988
  circle C17 centre (98.0736, -25.0791) radius 5.3988
  circle C18 centre (10.7976, -3.4838) radius 5.3988
  circle C19 centre (23.2656, -3.4838) radius 5.3988
  circle C20 centre (35.7336, -3.4838) radius 5.3988
  circle C21 centre (48.2016, -3.4838) radius 5.3988
  circle C22 centre (60.6696, -3.4838) radius 5.3988
  circle C23 centre (73.1376, -3.4838) radius 5.3988
  circle C24 centre (85.6056, -3.4838) radius 5.3988
  circle C25 centre (98.0736, -3.4838) radius 5.3988
  circle C26 centre (29.4996, -35.8767) radius 5.3988
  circle C27 centre (41.9676, -35.8767) radius 5.3988
  circle C28 centre (54.4356, -35.8767) radius 5.3988
  circle C29 centre (66.9036, -35.8767) radius 5.3988
  circle C30 centre (79.3716, -35.8767) radius 5.3988
  circle C31 centre (91.8396, -35.8767) radius 5.3988
  circle C32 centre (17.0316, -14.2814) radius 5.3988
  circle C33 centre (29.4996, -14.2814) radius 5.3988
  circle C34 centre (41.9676, -14.2814) radius 5.3988
  circle C35 centre (54.4356, -14.2814) radius 5.3988
  circle C36 centre (66.9036, -14.2814) radius 5.3988
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  point P7 (10.7976, -46.6743)
  point P22 (10.7976, -46.6743)
  point P6 (17.0316, -35.8767)
  point P14 (17.0316, -35.8767)
  point P15 (10.7976, -46.6743)
  point P9 (10.7976, -41.2755)
  point P13 (17.0316, -35.8767)
  point P16 (17.0316, -30.4779)
  point P17 (17.0316, -41.2755)
  point P8 (17.0316, -46.6743)
  point P11 (10.7976, -52.0731)
  tangent L5 C1
  tangent C1 L12
  coincident P7 P22
  perpendicular L7 L11
  coincident P6 P14
  coincident P15 P22
  coincident P9 C1
  perpendicular L7 L8
  perpendicular L10 L12
  coincident P13 P14
  coincident P16 C2
  parallel L6 L11
  midpoint P17 L11
  dimension "d247" radius C1 = 5.3988 (= "radius")
  dimension "d248" distance P7 P8 = 6.234 (= "Linear Dimension-2")
  dimension "d249" distance P6 P8 = 10.7976 (= "2 * radius")
  dimension "d250" diameter C2 = 10.7976 (= "2 * radius")
  dimension "d251" distance P7 P11 = 5.3988 (= "radius")
  dimension "d255" R-Pattern1-vDistance = 21.5952 (= "4 * radius")
  dimension "d259" R-Pattern2-vDistance = -21.5952 (= "-4 * radius")
sketch "Front inside" plane through (0, 0, -6.234) normal (0, 0, -1) x axis (-1, 0, 0)
  line L1 (0, 6.234) -> (0, -56.3921)
  line L2 (-108.8712, -56.3921) -> (-108.8712, 6.234)
  line L3 (0, -56.3921) -> (-108.8712, -56.3921)
  line L4 (-85.6056, -7.083) -> (-91.8396, -7.083)
  line L5 (-91.8396, -3.4838) -> (-98.0736, -3.4838)
  line L6 (-91.8396, -12.4818) -> (-91.8396, -7.083)
  line L7 (-91.8396, -1.6842) -> (-91.8396, -7.083)
  line L8 (-85.6056, -17.8807) -> (-85.6056, -7.083)
  line L9 (-91.8396, -7.083) -> (-91.8396, -3.4838)
  line L10 (-85.6056, -23.2795) -> (-85.6056, -17.8807)
  line L11 (-91.8396, -14.2814) -> (-91.8396, -3.4838)
  line L12 (-85.6056, -12.4818) -> (-85.6056, -17.8807)
  line L13 (-79.3716, -7.083) -> (-79.3716, -3.4838)
  line L14 (-79.3716, -12.4818) -> (-79.3716, -7.083)
  line L15 (-66.9036, -7.083) -> (-66.9036, -3.4838)
  line L16 (-66.9036, -12.4818) -> (-66.9036, -7.083)
  line L17 (-54.4356, -7.083) -> (-54.4356, -3.4838)
  line L18 (-54.4356, -12.4818) -> (-54.4356, -7.083)
  line L19 (-41.9676, -7.083) -> (-41.9676, -3.4838)
  line L20 (-41.9676, -12.4818) -> (-41.9676, -7.083)
  line L21 (-29.4996, -7.083) -> (-29.4996, -3.4838)
  line L22 (-29.4996, -12.4818) -> (-29.4996, -7.083)
  line L23 (-17.0316, -7.083) -> (-17.0316, -3.4838)
  line L24 (-17.0316, -12.4818) -> (-17.0316, -7.083)
  line L25 (-91.8396, -28.6783) -> (-91.8396, -25.0791)
  line L26 (-91.8396, -34.0771) -> (-91.8396, -28.6783)
  line L27 (-79.3716, -28.6783) -> (-79.3716, -25.0791)
  line L28 (-79.3716, -34.0771) -> (-79.3716, -28.6783)
  line L29 (-66.9036, -28.6783) -> (-66.9036, -25.0791)
  line L30 (-66.9036, -34.0771) -> (-66.9036, -28.6783)
  line L31 (-54.4356, -28.6783) -> (-54.4356, -25.0791)
  line L32 (-54.4356, -34.0771) -> (-54.4356, -28.6783)
  line L33 (-41.9676, -28.6783) -> (-41.9676, -25.0791)
  line L34 (-41.9676, -34.0771) -> (-41.9676, -28.6783)
  line L35 (-29.4996, -28.6783) -> (-29.4996, -25.0791)
  line L36 (-29.4996, -34.0771) -> (-29.4996, -28.6783)
  line L37 (-17.0316, -28.6783) -> (-17.0316, -25.0791)
  line L38 (-17.0316, -34.0771) -> (-17.0316, -28.6783)
  line L39 (-91.8396, -50.2735) -> (-91.8396, -46.6743)
  line L40 (-91.8396, -55.6723) -> (-91.8396, -50.2735)
  line L41 (-79.3716, -50.2735) -> (-79.3716, -46.6743)
  line L42 (-79.3716, -55.6723) -> (-79.3716, -50.2735)
  line L43 (-66.9036, -50.2735) -> (-66.9036, -46.6743)
  line L44 (-66.9036, -55.6723) -> (-66.9036, -50.2735)
  line L45 (-54.4356, -50.2735) -> (-54.4356, -46.6743)
  line L46 (-54.4356, -55.6723) -> (-54.4356, -50.2735)
  line L47 (-41.9676, -50.2735) -> (-41.9676, -46.6743)
  line L48 (-41.9676, -55.6723) -> (-41.9676, -50.2735)
  line L49 (-29.4996, -50.2735) -> (-29.4996, -46.6743)
  line L50 (-29.4996, -55.6723) -> (-29.4996, -50.2735)
  line L51 (-17.0316, -50.2735) -> (-17.0316, -46.6743)
  line L52 (-17.0316, -55.6723) -> (-17.0316, -50.2735)
  line L53 (-79.3716, -14.2814) -> (-79.3716, -3.4838)
  line L54 (-79.3716, -1.6842) -> (-79.3716, -7.083)
  line L55 (-66.9036, -14.2814) -> (-66.9036, -3.4838)
  line L56 (-66.9036, -1.6842) -> (-66.9036, -7.083)
  line L57 (-54.4356, -14.2814) -> (-54.4356, -3.4838)
  line L58 (-54.4356, -1.6842) -> (-54.4356, -7.083)
  line L59 (-41.9676, -14.2814) -> (-41.9676, -3.4838)
  line L60 (-41.9676, -1.6842) -> (-41.9676, -7.083)
  line L61 (-29.4996, -14.2814) -> (-29.4996, -3.4838)
  line L62 (-29.4996, -1.6842) -> (-29.4996, -7.083)
  line L63 (-17.0316, -14.2814) -> (-17.0316, -3.4838)
  line L64 (-17.0316, -1.6842) -> (-17.0316, -7.083)
  line L65 (-91.8396, -35.8767) -> (-91.8396, -25.0791)
  line L66 (-91.8396, -23.2795) -> (-91.8396, -28.6783)
  line L67 (-79.3716, -35.8767) -> (-79.3716, -25.0791)
  line L68 (-79.3716, -23.2795) -> (-79.3716, -28.6783)
  line L69 (-66.9036, -35.8767) -> (-66.9036, -25.0791)
  line L70 (-66.9036, -23.2795) -> (-66.9036, -28.6783)
  line L71 (-54.4356, -35.8767) -> (-54.4356, -25.0791)
  line L72 (-54.4356, -23.2795) -> (-54.4356, -28.6783)
  line L73 (-41.9676, -35.8767) -> (-41.9676, -25.0791)
  line L74 (-41.9676, -23.2795) -> (-41.9676, -28.6783)
  line L75 (-29.4996, -35.8767) -> (-29.4996, -25.0791)
  line L76 (-29.4996, -23.2795) -> (-29.4996, -28.6783)
  line L77 (-17.0316, -35.8767) -> (-17.0316, -25.0791)
  line L78 (-17.0316, -23.2795) -> (-17.0316, -28.6783)
  line L79 (-91.8396, -57.4719) -> (-91.8396, -46.6743)
  line L80 (-91.8396, -44.8747) -> (-91.8396, -50.2735)
  line L81 (-79.3716, -57.4719) -> (-79.3716, -46.6743)
  line L82 (-79.3716, -44.8747) -> (-79.3716, -50.2735)
  line L83 (-66.9036, -57.4719) -> (-66.9036, -46.6743)
  line L84 (-66.9036, -44.8747) -> (-66.9036, -50.2735)
  line L85 (-54.4356, -57.4719) -> (-54.4356, -46.6743)
  line L86 (-54.4356, -44.8747) -> (-54.4356, -50.2735)
  line L87 (-41.9676, -57.4719) -> (-41.9676, -46.6743)
  line L88 (-41.9676, -44.8747) -> (-41.9676, -50.2735)
  line L89 (-29.4996, -57.4719) -> (-29.4996, -46.6743)
  line L90 (-29.4996, -44.8747) -> (-29.4996, -50.2735)
  line L91 (-17.0316, -57.4719) -> (-17.0316, -46.6743)
  line L92 (-17.0316, -44.8747) -> (-17.0316, -50.2735)
  line L93 (-73.1376, -23.2795) -> (-73.1376, -17.8807)
  line L94 (-73.1376, -12.4818) -> (-73.1376, -17.8807)
  line L95 (-60.6696, -23.2795) -> (-60.6696, -17.8807)
  line L96 (-60.6696, -12.4818) -> (-60.6696, -17.8807)
  line L97 (-48.2016, -23.2795) -> (-48.2016, -17.8807)
  line L98 (-48.2016, -12.4818) -> (-48.2016, -17.8807)
  line L99 (-35.7336, -23.2795) -> (-35.7336, -17.8807)
  line L100 (-35.7336, -12.4818) -> (-35.7336, -17.8807)
  line L101 (-23.2656, -23.2795) -> (-23.2656, -17.8807)
  line L102 (-23.2656, -12.4818) -> (-23.2656, -17.8807)
  line L103 (-10.7976, -23.2795) -> (-10.7976, -17.8807)
  line L104 (-10.7976, -12.4818) -> (-10.7976, -17.8807)
  line L105 (-85.6056, -44.8747) -> (-85.6056, -39.4759)
  line L106 (-85.6056, -34.0771) -> (-85.6056, -39.4759)
  line L107 (-73.1376, -44.8747) -> (-73.1376, -39.4759)
  line L108 (-73.1376, -34.0771) -> (-73.1376, -39.4759)
  line L109 (-60.6696, -44.8747) -> (-60.6696, -39.4759)
  line L110 (-60.6696, -34.0771) -> (-60.6696, -39.4759)
  line L111 (-48.2016, -44.8747) -> (-48.2016, -39.4759)
  line L112 (-48.2016, -34.0771) -> (-48.2016, -39.4759)
  line L113 (-35.7336, -44.8747) -> (-35.7336, -39.4759)
  line L114 (-35.7336, -34.0771) -> (-35.7336, -39.4759)
  line L115 (-23.2656, -44.8747) -> (-23.2656, -39.4759)
  line L116 (-23.2656, -34.0771) -> (-23.2656, -39.4759)
  line L117 (-10.7976, -44.8747) -> (-10.7976, -39.4759)
  line L118 (-10.7976, -34.0771) -> (-10.7976, -39.4759)
  line L119 (-98.0736, -23.2795) -> (-98.0736, -17.8807)
  line L120 (-98.0736, -12.4818) -> (-98.0736, -17.8807)
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  point P9 (-91.8396, -3.4838)
  point P10 (-91.8396, -3.4838)
  point P11 (-91.8396, -7.083)
  point P12 (-91.8396, -7.083)
  point P20 (-85.6056, -17.8807)
  point P21 (-85.6056, -17.8807)
  point P17 (-85.6056, -17.8807)
  point P13 (-91.8396, -12.4818)
  point P7 (-91.8396, -1.6842)
  point P19 (-85.6056, -7.083)
  point P16 (-85.6056, -12.4818)
  point P18 (-85.6056, -23.2795)
  coincident P9 P10
  perpendicular L5 L9
  coincident P11 P12
  parallel L6 L11
  parallel L7 L11
  perpendicular L4 L11
  equal L4 L5
  perpendicular L4 L8
  coincident P20 P21
  parallel L8 L12
  coincident P17 P21
  parallel L8 L10
  dimension "d276" distance P10 P11 = 3.5992 (= "Linear Dimension-8")
  dimension "d277" diameter = 10.7976 (= "2 * radius")
  dimension "d278" distance P11 P13 = 5.3988 (= "radius")
  dimension "d279" distance P7 P11 = 5.3988 (= "radius")
  dimension "d280" distance P19 P20 = 10.7976 (= "2 * radius")
  dimension "d281" diameter = 10.7976 (= "2 * radius")
  dimension "d282" distance P16 P20 = 5.3988 (= "radius")
  dimension "d283" distance P17 P18 = 5.3988 (= "radius")
  dimension "d287" R-Pattern1-vDistance = -21.5952 (= "-4 * radius")
  dimension "d291" R-Pattern2-vDistance = 21.5952 (= "4 * radius")
  dimension "d295" R-Pattern3-vDistance = -21.5952 (= "-4 * radius")
revolve "Revolve81" sketch "Front outside" AlongAngle 360
revolve "Revolve32" sketch "Front outside" AlongAngle 360
revolve "Revolve33" sketch "Front outside" AlongAngle 360
revolve "Revolve34" sketch "Front outside" AlongAngle 360
revolve "Revolve35" sketch "Front outside" AlongAngle 360
revolve "Revolve36" sketch "Front outside" AlongAngle 360
revolve "Revolve37" sketch "Front outside" AlongAngle 360
revolve "Revolve38" sketch "Front outside" AlongAngle 360
revolve "Revolve39" sketch "Front outside" AlongAngle 360
revolve "Revolve40" sketch "Front outside" AlongAngle 360
revolve "Revolve41" sketch "Front outside" AlongAngle 360
revolve "Revolve42" sketch "Front outside" AlongAngle 360
revolve "Revolve43" sketch "Front outside" AlongAngle 360
revolve "Revolve44" sketch "Front outside" AlongAngle 360
revolve "Revolve45" sketch "Front outside" AlongAngle 360
revolve "Revolve82" sketch "Front inside" AlongAngle 360
revolve "Revolve46" sketch "Front inside" AlongAngle 360
revolve "Revolve48" sketch "Front inside" AlongAngle 360
revolve "Revolve49" sketch "Front inside" AlongAngle 360
revolve "Revolve50" sketch "Front inside" AlongAngle 360
revolve "Revolve51" sketch "Front inside" AlongAngle 360
revolve "Revolve52" sketch "Front inside" AlongAngle 360
revolve "Revolve53" sketch "Front inside" AlongAngle 360
revolve "Revolve54" sketch "Front inside" AlongAngle 360
revolve "Revolve55" sketch "Front inside" AlongAngle 360
revolve "Revolve56" sketch "Front inside" AlongAngle 360
revolve "Revolve57" sketch "Front inside" AlongAngle 360
revolve "Revolve58" sketch "Front inside" AlongAngle 360
revolve "Revolve59" sketch "Front inside" AlongAngle 360
revolve "Revolve60" sketch "Front inside" AlongAngle 360
sketch "Switch" plane through (0, 0, 0) normal (0, 0, 1) x axis (1, 0, 0)
  line L1 (108.8712, -56.3921) -> (0, -56.3921)
  line L2 (108.8712, 6.234) -> (108.8712, -56.3921)
  line L3 (0, 6.234) -> (108.8712, 6.234)
  line L4 (0, -56.3921) -> (0, 6.234)
  line L5 (43.4356, -21.4799) -> (54.4356, -21.4799)
  line L6 (43.4356, -20.3799) -> (43.4356, -21.4799)
  line L7 (43.4356, -22.5799) -> (43.4356, -21.4799)
  line L8 (44.3957, -20.3799) -> (43.4356, -20.3799)
  line L9 (44.3957, -22.5799) -> (43.4356, -22.5799)
  line L10 (54.4356, -26.4799) -> (54.4356, -21.4799)
  line L11 (64.4755, -20.3799) -> (65.4356, -20.3799)
  line L12 (65.4356, -22.5799) -> (65.4356, -21.4799)
  line L13 (65.4356, -20.3799) -> (65.4356, -21.4799)
  line L14 (65.4356, -21.4799) -> (54.4356, -21.4799)
  line L15 (64.4755, -22.5799) -> (65.4356, -22.5799)
  line L16 (54.4356, -56.3921) -> (54.4356, 6.234)
  circle C1 centre (54.4356, -21.4799) radius 10.1
  circle C2 centre (54.4356, -21.4799) radius 12.6
  circle C3 centre (54.4356, -21.4799) radius 11.75
  circle C4 centre (54.4356, -21.4799) radius 7.1984
  point P6 (54.4356, -21.4799)
  point P7 (54.4356, -21.4799)
  point P10 (54.4356, -21.4799)
  point P14 (44.3957, -20.3799)
  point P15 (44.3957, -22.5799)
  point P16 (54.4356, -21.4799)
  point P23 (54.4356, -21.4799)
  point P11 (43.4356, -21.4799)
  point P21 (65.4356, -21.4799)
  point P12 (43.4356, -20.3799)
  point P19 (65.4356, -20.3799)
  point P13 (43.4356, -22.5799)
  point P22 (65.4356, -22.5799)
  point P20 (64.4755, -20.3799)
  point P18 (64.4755, -22.5799)
  point P24 (54.4356, 6.234)
  point P25 (54.4356, -56.3921)
  point P27 (54.4356, -14.2814)
  point P28 (48.2016, -25.0791)
  point P26 (60.6696, -25.0791)
  point P29 (54.4356, -21.4799)
  point P17 (54.4356, -26.4799)
  coincident P6 P7
  horizontal L5
  coincident P6 P10
  perpendicular L5 L6
  perpendicular L5 L7
  coincident C1 P14
  perpendicular L6 L8
  coincident C1 P15
  perpendicular L7 L9
  coincident P6 P16
  perpendicular L5 L10
  symmetric P10 L10 P23
  symmetric P11 L10 P21
  symmetric P12 L10 P19
  symmetric P13 L10 P22
  symmetric P14 L10 P20
  symmetric P15 L10 P18
  midpoint L3 P24
  midpoint L1 P25
  concentric C1 C3
  coincident P27 C4
  coincident P28 C4
  coincident P26 C4
  coincident P23 P29
  dimension "d326" diameter C1 = 20.2
  dimension "d327" = 2.5
  dimension "d340" diameter C3 = 23.5
  dimension "d490" distance P10 P11 = 11
  dimension "d491" distance P11 P12 = 1.1
  dimension "d492" distance P11 P13 = 1.1
  dimension "d493" distance P16 P17 = 5
position "Position7"
delete_face "DeleteFace1"
delete_face "DeleteFace2"
sketch "Feet" plane through (0, 6.234, 0) normal (0, 1, 0) x axis (-1, 0, 0)
  line L1 (0, 0) -> (0, -127.4117)
  line L2 (-108.8712, 0) -> (0, 0)
  line L3 (-108.8712, -127.4117) -> (-108.8712, 0)
  line L4 (0, -127.4117) -> (-108.8712, -127.4117)
  line L5 (-54.4356, 0) -> (-54.4356, -127.4117)
  line L6 (0, -63.7059) -> (-108.8712, -63.7059)
  circle C1 centre (-17.8988, -17.8988) radius 12.5
  circle C2 centre (-17.8988, -17.8988) radius 10
  circle C3 centre (-90.9724, -17.8988) radius 12.5
  circle C4 centre (-90.9724, -17.8988) radius 10
  circle C5 centre (-17.8988, -109.5129) radius 12.5
  circle C6 centre (-17.8988, -109.5129) radius 10
  circle C7 centre (-90.9724, -109.5129) radius 12.5
  circle C8 centre (-90.9724, -109.5129) radius 10
  point P8 (-54.4356, -127.4117)
  point P9 (-54.4356, 0)
  point P10 (-108.8712, -63.7059)
  point P11 (0, -63.7059)
  point P6 (-17.8988, -17.8988)
  concentric C1 C2
  midpoint L4 P8
  midpoint L2 P9
  midpoint L3 P10
  midpoint L1 P11
  symmetric C1 L5 C3
  symmetric C2 L5 C4
  symmetric C1 L6 C5
  symmetric C2 L6 C6
  symmetric L6 C3 C7
  symmetric L6 C4 C8
  dimension "d347" diameter C1 = 25
  dimension "d348" diameter C2 = 20
  dimension "d391" distance L2 P6 = 17.8988 (= "12.50 mm + radius")
  dimension "d392" distance L1 P6 = 17.8988 (= "12.50 mm + radius")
